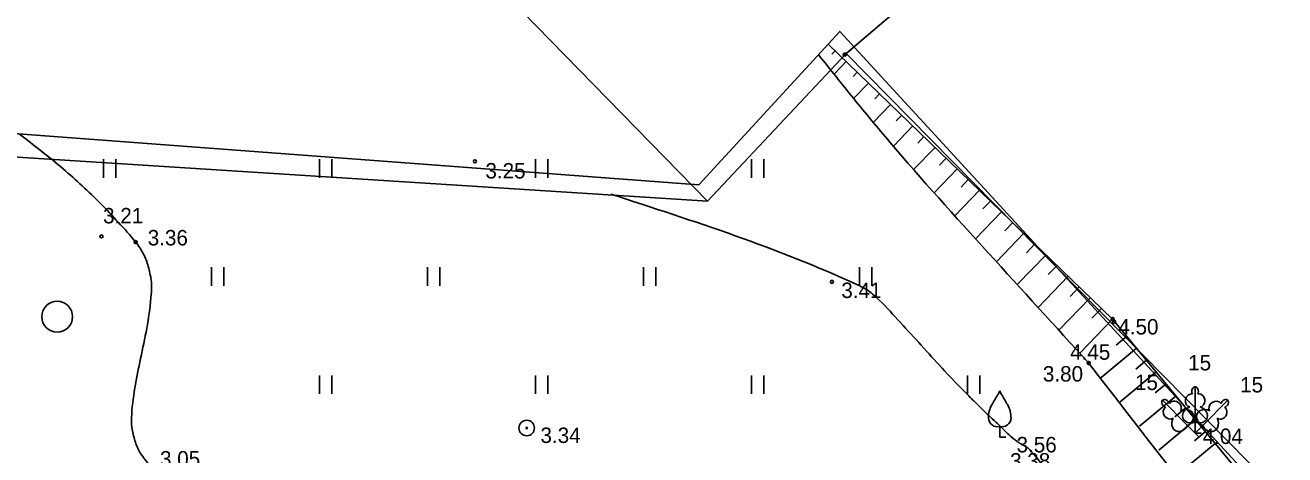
# Model space of a CAD drawing. Extents: x 519536 to 519949, y 326041 to 326519.
# Drawn here: x 519656.46 to 519697.28, y 326408.03 to 326421.94 of the extents above; entities that cross this region are included whole.
import ezdxf

# ---------------------------------------------------------------- set-up
doc = ezdxf.new("R2010")
doc.units = 0
for name, color, linetype in [('BUVE_ELEM_####_####_#', 7, 'Continuous'), ('NORB_ZOGS_KBST_####_#', 7, 'Continuous'), ('NORB_ZOGS_SBST_####_#', 7, 'Continuous'), ('NORB_ZOGS_ZBET_####_#', 7, 'Continuous'), ('RAMI_UZMR_####_####_#', 7, 'Continuous'), ('RELJ_AATZ_####_TKST_#', 7, 'Continuous'), ('RELJ_ELEM_####_####_#', 7, 'Continuous'), ('RELJ_HORZ_PAMT_####_#', 7, 'Continuous'), ('RELJ_NOGA_####_####_#', 7, 'Continuous'), ('RELJ_NOGL_####_####_#', 7, 'Continuous'), ('ROBZ_UZMR_####_####_#', 7, 'Continuous'), ('TERT_DIAM_####_TKST_#', 7, 'Continuous'), ('TERT_ELEM_####_####_#', 7, 'Continuous'), ('TERT_KONT_####_####_#', 7, 'Continuous')]:
    doc.layers.add(name, color=color, linetype=linetype)

msp = doc.modelspace()

# ---------------------------------------------------------------- linework, layer by layer
at = {"layer": 'BUVE_ELEM_####_####_#'}
for radius in [0.25, 0.0225]:
    msp.add_circle((519672.716, 326408.897), radius, dxfattribs=at)
at = {"layer": 'NORB_ZOGS_KBST_####_#'}
msp.add_lwpolyline([(519704.591, 326396.84), (519691.702, 326412.425)], dxfattribs=at)
at = {"layer": 'NORB_ZOGS_SBST_####_#'}
msp.add_lwpolyline([(519683.325, 326421.237), (519682.962, 326420.927)], dxfattribs=at)
at = {"layer": 'NORB_ZOGS_ZBET_####_#'}
msp.add_lwpolyline([(519691.702, 326412.425), (519682.483, 326421.328)], dxfattribs=at)
at = {"layer": 'RAMI_UZMR_####_####_#'}
msp.add_lwpolyline([(519606.503, 326354.123), (519598.183, 326371.842), (519589.598, 326374.981), (519581.568, 326396.559), (519571.96, 326403.209), (519550.477, 326420.838), (519546.03, 326425.168), (519546.311, 326425.748), (519562.267, 326424.735), (519567.537, 326424.176), (519622.695, 326420.6), (519656.101, 326418.428), (519678.291, 326416.771), (519682.862, 326421.74), (519706.678, 326395.86), (519695.81, 326390.264), (519680.586, 326385.663), (519636.229, 326369.014), (519636.521, 326358.648)], dxfattribs=at)
at = {"layer": 'RELJ_ELEM_####_####_#'}
for centre in [(519683.025, 326420.991), (519671.037, 326417.533), (519658.937, 326415.1), (519660.042, 326414.916), (519682.606, 326413.629), (519691.702, 326412.425), (519691.754, 326412.33), (519690.926, 326411.003)]:
    msp.add_circle(centre, 0.05, dxfattribs=at)
at = {"layer": 'RELJ_HORZ_PAMT_####_#'}
for points in [[(519687.131, 326409.845), (519686.777, 326410.206), (519686.09, 326410.93), (519685.418, 326411.667), (519684.743, 326412.403), (519684.049, 326413.124), (519683.704, 326413.396), (519683.417, 326413.542), (519675.44, 326416.47)], [(519690.495, 326406.192), (519689.901, 326407.053), (519689.469, 326407.63), (519689.016, 326408.193), (519688.904, 326408.288), (519688.775, 326408.364), (519688.644, 326408.436), (519688.525, 326408.523), (519688.08, 326408.935), (519687.638, 326409.351), (519687.203, 326409.773), (519687.131, 326409.845)]]:
    msp.add_spline(points, degree=3, dxfattribs=at)
at = {"layer": 'RELJ_NOGA_####_####_#'}
for p, q in [((519682.71, 326421.108), (519682.606, 326421)), ((519683.07, 326420.761), (519682.677, 326420.354)), ((519683.43, 326420.414), (519683.299, 326420.278)), ((519683.789, 326420.066), (519683.308, 326419.568)), ((519684.149, 326419.719), (519683.992, 326419.557)), ((519684.509, 326419.372), (519683.947, 326418.79)), ((519684.868, 326419.024), (519684.689, 326418.839)), ((519685.228, 326418.677), (519684.597, 326418.023)), ((519685.588, 326418.33), (519685.389, 326418.124)), ((519685.947, 326417.982), (519685.255, 326417.265)), ((519686.307, 326417.635), (519686.091, 326417.411)), ((519686.667, 326417.288), (519685.918, 326416.513)), ((519687.026, 326416.94), (519686.794, 326416.7)), ((519687.386, 326416.593), (519686.587, 326415.766)), ((519687.746, 326416.246), (519687.499, 326415.99)), ((519688.105, 326415.898), (519687.26, 326415.023)), ((519688.465, 326415.551), (519688.205, 326415.281)), ((519688.825, 326415.204), (519687.935, 326414.282)), ((519689.544, 326414.509), (519688.611, 326413.543)), ((519689.184, 326414.856), (519688.911, 326414.573)), ((519689.904, 326414.162), (519689.617, 326413.865)), ((519690.263, 326413.814), (519689.288, 326412.804)), ((519690.623, 326413.467), (519690.324, 326413.157)), ((519690.983, 326413.12), (519689.964, 326412.064)), ((519691.342, 326412.772), (519691.03, 326412.449)), ((519691.702, 326412.425), (519690.637, 326411.323)), ((519691.845, 326412.252), (519691.844, 326412.252)), ((519692.164, 326411.867), (519691.816, 326411.579)), ((519692.482, 326411.482), (519691.319, 326410.519)), ((519692.801, 326411.096), (519692.451, 326410.807)), ((519693.119, 326410.711), (519691.947, 326409.741)), ((519693.438, 326410.326), (519693.085, 326410.033)), ((519693.757, 326409.94), (519692.573, 326408.962)), ((519694.394, 326409.17), (519693.198, 326408.181)), ((519694.075, 326409.555), (519693.719, 326409.26)), ((519694.713, 326408.784), (519694.352, 326408.486)), ((519695.031, 326408.399), (519693.822, 326407.399))]:
    msp.add_line(p, q, dxfattribs=at)
at = {"layer": 'RELJ_NOGL_####_####_#'}
for points in [[(519690.926, 326411.003), (519687.681, 326414.56), (519684.481, 326418.157), (519683.893, 326418.856), (519683.313, 326419.562), (519682.169, 326420.986)], [(519690.926, 326411.003), (519701.164, 326398.42), (519703.254, 326396.147)]]:
    msp.add_spline(points, degree=3, dxfattribs=at)
at = {"layer": 'ROBZ_UZMR_####_####_#'}
for p, q in [((519678.574, 326416.24), (519652.995, 326442.405)), ((519695.491, 326431.618), (519683.072, 326421.021)), ((519678.574, 326416.24), (519547.147, 326424.602)), ((519683.072, 326421.021), (519678.574, 326416.24)), ((519700.236, 326403.605), (519683.072, 326421.021))]:
    msp.add_line(p, q, dxfattribs=at)
at = {"layer": 'TERT_ELEM_####_####_#'}
for p, q in [((519659, 326417), (519659, 326417.6)), ((519659.4, 326417), (519659.4, 326417.6)), ((519666, 326417), (519666, 326417.6)), ((519666.4, 326417), (519666.4, 326417.6)), ((519673, 326417), (519673, 326417.6)), ((519673.4, 326417), (519673.4, 326417.6)), ((519680, 326417), (519680, 326417.6)), ((519680.4, 326417), (519680.4, 326417.6)), ((519662.5, 326413.5), (519662.5, 326414.1)), ((519662.9, 326413.5), (519662.9, 326414.1)), ((519669.5, 326413.5), (519669.5, 326414.1)), ((519669.9, 326413.5), (519669.9, 326414.1)), ((519676.5, 326413.5), (519676.5, 326414.1)), ((519676.9, 326413.5), (519676.9, 326414.1)), ((519683.5, 326413.5), (519683.5, 326414.1)), ((519683.9, 326413.5), (519683.9, 326414.1)), ((519666, 326410), (519666, 326410.6)), ((519666.4, 326410), (519666.4, 326410.6)), ((519673, 326410), (519673, 326410.6)), ((519673.4, 326410), (519673.4, 326410.6)), ((519680, 326410), (519680, 326410.6)), ((519680.4, 326410), (519680.4, 326410.6)), ((519687, 326410), (519687, 326410.6)), ((519687.4, 326410), (519687.4, 326410.6)), ((519688.044, 326408.949), (519688.044, 326408.597)), ((519694.131, 326408.98), (519694.376, 326408.735)), ((519694.376, 326409.082), (519694.376, 326408.735)), ((519694.621, 326408.98), (519694.376, 326408.735)), ((519694.376, 326408.735), (519694.517, 326408.876)), ((519688.044, 326408.597), (519688.244, 326408.597)), ((519694.376, 326408.735), (519694.576, 326408.735)), ((519694.376, 326408.735), (519694.517, 326408.594))]:
    msp.add_line(p, q, dxfattribs=at)
for points in [[(519694.376, 326410.235), (519694.376, 326409.082)], [(519694.466, 326410.003), (519694.465, 326410.004)], [(519693.315, 326409.796), (519694.131, 326408.98)], [(519693.543, 326409.695), (519693.542, 326409.695)], [(519695.437, 326409.796), (519694.621, 326408.98)], [(519695.336, 326409.568), (519695.336, 326409.569)]]:
    msp.add_lwpolyline(points, dxfattribs=at)
msp.add_circle((519657.5, 326412.5), 0.5, dxfattribs=at)
for centre, radius, start, end in [((519687.627, 326410.235), 0.439, 324.3837, 341.712), ((519688.461, 326410.235), 0.439, 198.288, 215.6163), ((519688.568, 326409.222), 0.89, 151.757, 179.9138), ((519700.669, 326402.201), 14.88, 148.4844, 149.9901), ((519675.419, 326402.201), 14.88, 30.0099, 31.5156), ((519687.52, 326409.222), 0.89, 0.0862, 28.243), ((519687.968, 326409.228), 0.29, 181.0782, 285.2823), ((519688.12, 326409.228), 0.29, 254.7177, 358.9218)]:
    msp.add_arc(centre, radius, start, end, dxfattribs=at)
for centre, major_axis, ratio, start_param, end_param in [((519694.248, 326409.79), (-0.039, -0.212), 0.861323, 3.141593, 6.283185), ((519694.376, 326410.085), (0, -0.15), 0.707107, 3.14537, 5.287485), ((519694.376, 326410.085), (0, -0.15), 0.707107, 0.995701, 3.137816), ((519694.504, 326409.79), (0.039, -0.212), 0.861323, 0, 3.141593), ((519693.422, 326409.69), (0.106, -0.106), 0.707107, 3.14537, 5.287485), ((519693.421, 326409.689), (0.106, -0.106), 0.707107, 0.995701, 3.137816), ((519693.721, 326409.572), (0.178, -0.123), 0.861323, 6.283185, 9.424778), ((519694.286, 326409.328), (0.307, 0.095), 0.814445, 1.570796, 4.752015), ((519694.466, 326409.328), (-0.307, 0.095), 0.814445, 1.531171, 4.712389), ((519695.031, 326409.572), (-0.178, -0.123), 0.861323, 3.141593, 6.283185), ((519695.331, 326409.689), (-0.106, -0.106), 0.707107, 3.14537, 5.287485), ((519695.33, 326409.69), (-0.106, -0.106), 0.707107, 0.995701, 3.137816), ((519693.539, 326409.39), (0.123, -0.178), 0.861323, 3.141593, 6.283185), ((519693.893, 326409.091), (0.15, 0.284), 0.814445, 1.570796, 4.752015), ((519694.02, 326409.218), (-0.284, -0.15), 0.814445, 1.531171, 4.712389), ((519694.732, 326409.218), (0.284, -0.15), 0.814445, 1.570796, 4.752015), ((519694.859, 326409.091), (-0.15, 0.284), 0.814445, 1.531171, 4.712389), ((519695.213, 326409.39), (-0.123, -0.178), 0.861323, 6.283185, 9.424778)]:
    msp.add_ellipse(centre, major_axis=major_axis, ratio=ratio, start_param=start_param, end_param=end_param, dxfattribs=at)
at = {"layer": 'TERT_KONT_####_####_#'}
msp.add_spline([(519656.276, 326418.415), (519657.694, 326417.286), (519658.907, 326416.161), (519659.485, 326415.554), (519660.042, 326414.916), (519660.292, 326414.538), (519660.452, 326414.128), (519660.507, 326413.905), (519660.548, 326413.68), (519660.55, 326413.232), (519660.23, 326411.271), (519659.915, 326409.343), (519659.92, 326408.916), (519659.963, 326408.702), (519660.02, 326408.488), (519660.089, 326408.29), (519660.184, 326408.105), (519660.44, 326407.758), (519669.963, 326403.559), (519684.467, 326393.28), (519688.263, 326389.935), (519687.074, 326387.624)], degree=3, dxfattribs=at)

# ---------------------------------------------------------------- texts
at = {"layer": 'RELJ_AATZ_####_TKST_#'}
for s, p in [('3.25', (519671.378, 326416.976)), (' 3.21', (519658.802, 326415.522)), ('3.36', (519660.435, 326414.809)), ('3.41', (519682.912, 326413.106)), (' 4.50', (519691.702, 326411.925)), ('4.45', (519690.326, 326411.108)), (' 3.80', (519689.258, 326410.402)), ('3.34', (519673.162, 326408.413)), (' 4.04', (519694.437, 326408.379)), ('3.56', (519688.591, 326408.108)), ('3.05', (519660.833, 326407.651)), (' 3.38', (519688.195, 326407.585))]:
    msp.add_text(s, height=0.5, dxfattribs=at).set_placement(p)
at = {"layer": 'TERT_DIAM_####_TKST_#'}
for p in [(519694.151, 326410.761), (519692.428, 326410.127), (519695.835, 326410.048)]:
    msp.add_text('15', height=0.5, dxfattribs=at).set_placement(p)

doc.saveas('drawing.dxf')
